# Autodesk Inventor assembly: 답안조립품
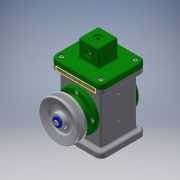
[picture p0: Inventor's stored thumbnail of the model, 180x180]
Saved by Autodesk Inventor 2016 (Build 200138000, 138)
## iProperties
Created: 2017-08
Part Number: 답안조립품
Material: 일반
Document SubType Name: Assembly
Designer: USER
Author: USER
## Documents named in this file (18)
- C:\Users\USER\Desktop\470808V1018\답안조립품.iam
- C:\Users\USER\Desktop\470808V1018\본체.ipt
- C:\Users\USER\Desktop\470808V1018\E-링.ipt
- C:\Users\USER\Desktop\470808V1018\V-벨트풀리.ipt
- C:\Users\USER\Desktop\470808V1018\덮개.ipt
- C:\Users\USER\Desktop\470808V1018\뒤커버.ipt
- C:\Users\USER\Desktop\470808V1018\링크.ipt
- C:\Users\USER\Desktop\470808V1018\베어링 17 x 40 x 12.ipt
- C:\Users\USER\Desktop\470808V1018\볼트 M4 x 8.ipt
- C:\Users\USER\Desktop\470808V1018\볼트 M4 x 10.ipt
- C:\Users\USER\Desktop\470808V1018\슬라이더.ipt
- C:\Users\USER\Desktop\470808V1018\앞커버.ipt
- C:\Users\USER\Desktop\470808V1018\오일 실 17 30 8.ipt
- C:\Users\USER\Desktop\470808V1018\와셔 4x16.ipt
- C:\Users\USER\Desktop\470808V1018\클레비스 핀 6 x 22.ipt
- 클레비스 핀 6 x 22.ipt
- C:\Users\USER\Desktop\470808V1018\키 4 x 4 x 12.ipt
- C:\Users\USER\Desktop\470808V1018\편심축.ipt
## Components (2 placed, 2 different names)
1. E-링:1
2. V-벨트풀리:1
